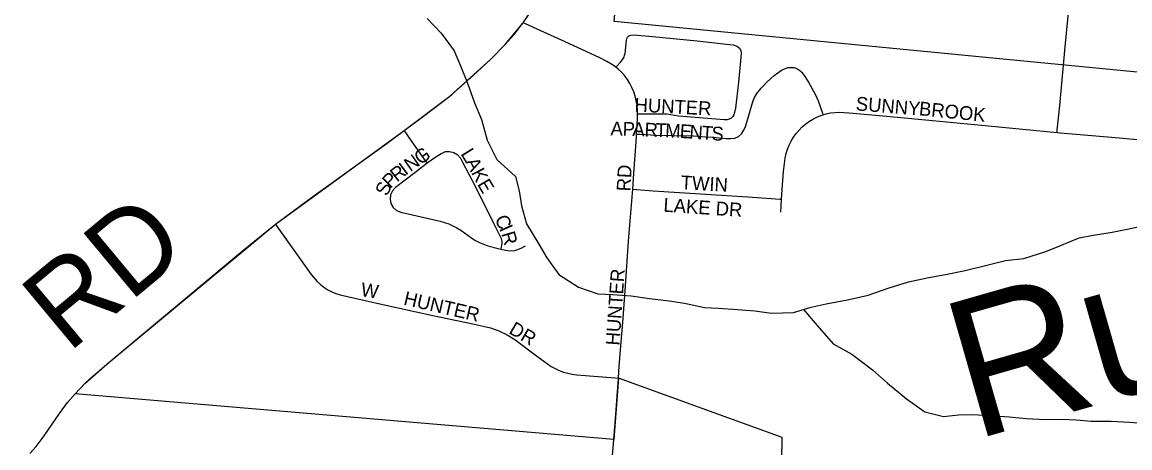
# Model space of a CAD drawing. Extents: x 1410790 to 1770854, y 566777 to 831614.
# Drawn here: x 1562528 to 1566542, y 678665 to 680208 of the extents above; entities that cross this region are included whole.
import ezdxf

# ---------------------------------------------------------------- set-up
doc = ezdxf.new("R2010")
doc.units = 0
for name, color, linetype in [('GM_X_City_Street', 7, 'Continuous'), ('GM_X_City_Street_Text', 7, 'Continuous'), ('GM_X_Corporation', 7, 'Continuous'), ('GM_X_County_Road', 7, 'Continuous'), ('GM_X_County_Road_Text', 7, 'Continuous'), ('GM_X_Minor_River', 7, 'Continuous'), ('GM_X_Minor_River_Text', 7, 'Continuous'), ('GM_X_Section', 7, 'Continuous')]:
    doc.layers.add(name, color=color, linetype=linetype)

msp = doc.modelspace()

# ---------------------------------------------------------------- linework, layer by layer
at = {"layer": 'GM_X_City_Street'}
for points in [[(1566278.5, 679807.9), (1566279.3, 679816.5), (1566287.8, 679906), (1566308, 680118.8), (1566322.3, 680267.4)], [(1564679.3, 680044.6), (1564670.4, 680051.4), (1564660.6, 680057.5), (1564646.1, 680065.8), (1564621.3, 680078.7), (1564493.8, 680137.6), (1564408.1, 680176.7), (1564352.3, 680201.4), (1564343.1, 680205.5)], [(1564679.3, 680044.6), (1564683.2, 680048.7), (1564696.7, 680063.1), (1564704.7, 680073.4), (1564709, 680081.2), (1564711.3, 680087.8), (1564712.8, 680094), (1564717.4, 680141.1), (1564718.7, 680148.2), (1564721.9, 680154), (1564727, 680158.3), (1564734.1, 680161.3), (1564744.2, 680161.7), (1564812.3, 680156.4), (1564973.8, 680140.1), (1565080.6, 680128.8), (1565104.7, 680125.6), (1565119.5, 680120.5), (1565127.8, 680113.5), (1565132.7, 680105.5), (1565133.7, 680096), (1565132.7, 680081), (1565123.8, 679990.2), (1565112.7, 679896.8), (1565109.5, 679880.6), (1565107.1, 679872.3), (1565103.1, 679865.6), (1565097.8, 679860), (1565090.5, 679855.8), (1565083, 679854.3), (1565071.4, 679853.5), (1564907.3, 679867.5), (1564892.3, 679870.2), (1564878.3, 679872.3), (1564862.7, 679874.2), (1564843.7, 679875), (1564770.9, 679874.2), (1564758, 679874)], [(1564758, 679874), (1564757.8, 679890), (1564756.2, 679906.6), (1564753.5, 679923.2), (1564749.4, 679939.5), (1564744.2, 679955.5), (1564737.8, 679971), (1564730.2, 679986), (1564721.4, 680000.3), (1564711.5, 680014), (1564700.2, 680026.5), (1564687.9, 680038), (1564679.3, 680044.6)], [(1564754.8, 679802.6), (1564766.7, 679801.8), (1564825.7, 679798), (1564881, 679797.3), (1564960.7, 679795.5), (1565003.8, 679792.9), (1565029.6, 679790.7), (1565078.6, 679785.9), (1565094.6, 679785.8), (1565110.1, 679787.6), (1565123.8, 679793.2), (1565134.9, 679803), (1565143.5, 679816), (1565149.4, 679830.4), (1565159.1, 679861.5), (1565173.1, 679911.8), (1565178, 679926.8), (1565181.7, 679935.3), (1565190.7, 679949.4), (1565206.4, 679968.2), (1565228, 679991.4), (1565252.6, 680014.2), (1565265.9, 680024.6), (1565280.3, 680034), (1565288.1, 680038), (1565296.5, 680041.4), (1565303.4, 680043.3), (1565310, 680044.2), (1565317, 680044.2), (1565323.9, 680043.4), (1565331.7, 680041.1), (1565338.8, 680038), (1565345.6, 680033.2), (1565352.4, 680026.4), (1565359, 680018.5), (1565377.1, 679990.4), (1565402, 679947.3), (1565408.2, 679933.5), (1565412.5, 679922.8), (1565427.7, 679877.9), (1565429.6, 679872.4)], [(1564754.8, 679802.6), (1564758.2, 679856.7), (1564758, 679874)], [(1565280.3, 679566), (1565282.6, 679601.1), (1565287.3, 679666.7), (1565293.5, 679715.5), (1565296.8, 679731.5), (1565301.4, 679747.3), (1565307.4, 679762.5), (1565314.7, 679777.2), (1565323.2, 679791.3), (1565332.9, 679804.5), (1565343.4, 679817.1), (1565354.9, 679828.9), (1565367.4, 679839.7), (1565381, 679849.3), (1565395.3, 679857.8), (1565410.3, 679865.2), (1565425.7, 679871.2), (1565429.6, 679872.4)], [(1565429.6, 679872.4), (1565441.6, 679876), (1565457.8, 679879.2), (1565474.2, 679881), (1565490.5, 679881.3), (1565539.7, 679878.1), (1565686.7, 679864.3), (1565801.1, 679853.5), (1566029.8, 679832.1), (1566278.5, 679807.9)], [(1563995.7, 679696.5), (1563978.1, 679721.5), (1563932.5, 679786), (1563917.8, 679807.5), (1563912.8, 679814.8)], [(1564740.4, 679602.9), (1564744.9, 679660), (1564754, 679791), (1564754.8, 679802.6)], [(1566278.5, 679807.9), (1566291.2, 679806.6), (1566503.7, 679788.8), (1566633.7, 679776.3)], [(1564264, 679385.2), (1564264.9, 679391.9), (1564267, 679406.3), (1564267, 679412.8), (1564266.3, 679418.2), (1564265.1, 679422.1), (1564236.5, 679480.8), (1564170.2, 679612), (1564125.4, 679699.2), (1564117.3, 679713.5), (1564106.6, 679725.6), (1564092.8, 679734.1), (1564077.1, 679738.4), (1564060.9, 679737.5), (1564046, 679731.2), (1564027.4, 679718.5), (1563995.7, 679696.5)], [(1563995.7, 679696.5), (1563950.4, 679662.2), (1563881.1, 679608.7), (1563869.7, 679597), (1563862.6, 679582.5), (1563861, 679566.3), (1563864.3, 679550.3), (1563872.3, 679536.1), (1563884.5, 679525.5), (1563899.7, 679519.7), (1564043, 679486.5), (1564058.7, 679482.1), (1564074.1, 679476.8), (1564089, 679470.2), (1564103.4, 679462.6), (1564117.3, 679454.1), (1564157, 679425.2), (1564170.9, 679416.8), (1564185.4, 679409.3), (1564215.8, 679397.6), (1564253.4, 679387.7), (1564264, 679385.2)], [(1564688.7, 678917.5), (1564691.6, 678962.3), (1564692.5, 678972.6), (1564695.4, 679005.3), (1564704.4, 679119.8), (1564713.2, 679234.3), (1564725.8, 679414.6), (1564740.4, 679602.9)], [(1564740.4, 679602.9), (1564756, 679601.7), (1564814.8, 679597.2), (1565157.4, 679574.3), (1565241.8, 679568.5), (1565273.7, 679566.4), (1565280.3, 679566)], [(1565277.2, 679519.2), (1565280.3, 679566)], [(1563445.5, 679475.2), (1563455.8, 679460.8), (1563575.6, 679293.5), (1563596.7, 679268.5), (1563608.5, 679257.1), (1563621.4, 679246.9), (1563635.2, 679238.1), (1563649.7, 679230.5), (1563664.8, 679224.2), (1563680.4, 679219.3), (1563824.3, 679187), (1564016.7, 679145.3), (1564161.1, 679114.5), (1564225, 679100), (1564255.9, 679089), (1564285.4, 679074.8), (1564313.2, 679057.4), (1564392.4, 678999), (1564431.4, 678969), (1564445.1, 678959.9), (1564459.4, 678952), (1564474.4, 678945.3), (1564489.8, 678939.7), (1564505.6, 678935.2), (1564521.6, 678931.6), (1564537.8, 678929.1), (1564676.5, 678918.5), (1564688.7, 678917.5)], [(1564264, 679385.2), (1564279.3, 679381.5), (1564295.4, 679379.5), (1564311.6, 679380), (1564324.5, 679383.4), (1564338.7, 679390.2), (1564351.7, 679397.6)], [(1564685.6, 678870.1), (1564686.4, 678882.2), (1564688.7, 678917.5)]]:
    msp.add_lwpolyline(points, dxfattribs=at)
at = {"layer": 'GM_X_Corporation'}
msp.add_lwpolyline([(1565279.2, 678536.4), (1565282.3, 678702.9), (1564688.7, 678917.5), (1564671.8, 678694.9), (1562719.4, 678861.1), (1562754.5, 678898), (1562834.8, 678968.3), (1563445.5, 679475.2), (1563912.8, 679814.8), (1564077.3, 679940), (1564226.4, 680074.3), (1564278.6, 680126.8), (1564343.1, 680205.5), (1564519.8, 680474.3)], dxfattribs=at)
at = {"layer": 'GM_X_County_Road'}
for points in [[(1564343.1, 680205.5), (1564387.9, 680270.9), (1564469.4, 680393.9), (1564519.8, 680474.3)], [(1563912.8, 679814.8), (1563982.8, 679866.9), (1564077.3, 679940), (1564086.6, 679947.2), (1564162.6, 680014.1), (1564226.4, 680074.3), (1564278.6, 680126.8), (1564311.4, 680163.9), (1564341.4, 680203.1), (1564343.1, 680205.5)], [(1563445.5, 679475.2), (1563571.2, 679568.6), (1563851.1, 679769), (1563912.8, 679814.8)], [(1562556, 678644.5), (1562578.1, 678669.3), (1562607.8, 678708.9), (1562663.5, 678790), (1562692.4, 678829.4), (1562719.4, 678861.1), (1562754.6, 678898.1), (1562772.8, 678914.9), (1562834.8, 678968.3), (1562960.5, 679073.5), (1563325.3, 679378.1), (1563439.8, 679470.9), (1563445.5, 679475.2)], [(1564314.6, 674908.5), (1564323.9, 675001), (1564340.4, 675164.4), (1564372.1, 675458.4), (1564397.7, 675703.6), (1564422.2, 675948.9), (1564463.2, 676407.2), (1564478.3, 676570.8), (1564499.5, 676799.7), (1564521.5, 677045.1), (1564554.4, 677388.5), (1564571.6, 677584.9), (1564602.8, 677928.6), (1564615.2, 678059.4), (1564633, 678239.1), (1564657.8, 678517), (1564671.8, 678694.9), (1564680.9, 678801.2), (1564685.6, 678870.1)]]:
    msp.add_lwpolyline(points, dxfattribs=at)
at = {"layer": 'GM_X_Minor_River'}
for points in [[(1563995.1, 680221.3), (1564046.4, 680168.6), (1564093.5, 680104), (1564116.7, 680049.7), (1564141.9, 679987.3), (1564167, 679915), (1564192.2, 679854.6), (1564213.2, 679780.3), (1564248.3, 679709.8), (1564315.4, 679649), (1564328.7, 679596.8)], [(1564328.7, 679596.8), (1564338, 679542.6), (1564355.1, 679476.4), (1564400.1, 679403.8), (1564429.5, 679353.4), (1564472.6, 679292.8), (1564543.9, 679247.9), (1564613.5, 679223), (1564667.3, 679220.3), (1564735.1, 679215.4), (1564800.9, 679206.6), (1564872.6, 679197.7), (1564928.4, 679188.9), (1565000.1, 679174), (1565051.9, 679171.3), (1565119.7, 679166.5), (1565183.5, 679161.7), (1565243.3, 679152.9), (1565323.2, 679155.9), (1565387.3, 679175.1), (1565441.3, 679186.4), (1565519.3, 679201.4), (1565593.4, 679218.4), (1565669.6, 679245.5), (1565739.7, 679266.6), (1565807.7, 679281.7), (1565879.7, 679294.8), (1565945.8, 679308), (1566023.8, 679327), (1566091.9, 679344.1), (1566157.9, 679351.3), (1566238, 679376.3), (1566288.2, 679397.7), (1566358.4, 679426.8), (1566410.4, 679436.1), (1566478.4, 679447.3), (1566538.4, 679458.5), (1566616.4, 679475.5)], [(1565359.1, 679166.6), (1565408.4, 679108.8), (1565467.5, 679042), (1565534.9, 679005.1), (1565610, 678948.1), (1565663.3, 678899.4), (1565732.4, 678842.5), (1565799.7, 678795.7), (1565867.4, 678778.8), (1565921.3, 678784.1), (1565973.2, 678785.4), (1566031.1, 678782.7), (1566104.9, 678777.8), (1566166.6, 678771), (1566236.5, 678768.1), (1566294.4, 678769.4), (1566348.2, 678766.7), (1566402, 678762), (1566473.9, 678761.1), (1566541.7, 678758.2), (1566599.5, 678753.5), (1566669.4, 678754.6), (1566733.1, 678741.8), (1566798.9, 678738.9)]]:
    msp.add_lwpolyline(points, dxfattribs=at)
at = {"layer": 'GM_X_Section'}
msp.add_lwpolyline([(1570366.9, 684817.2), (1570438.7, 684810.1), (1569973.9, 679696.7), (1564673.5, 680210.6), (1565148.5, 685333.7)], close=True, dxfattribs=at)

# ---------------------------------------------------------------- texts
at = {"layer": 'GM_X_City_Street_Text'}
for s, rotation, p in [('HUNTER', 357.0389, (1564746.3, 679884.2)), ('SUNNY', 355.2345, (1565547.6, 679888.6)), ('BROOK', 354.1724, (1565776.4, 679871)), ('A', 357.9562, (1564659.5, 679798.2)), ('P', 357.9507, (1564703.4, 679796.7)), ('A', 357.9605, (1564738.6, 679795.4)), ('R', 357.9477, (1564782.6, 679793.8)), ('T', 357.7596, (1564822.1, 679792.4)), ('M', 357.1212, (1564857.2, 679791.1)), ('E', 356.6095, (1564909.8, 679788.4)), ('N', 355.8552, (1564944.7, 679786.3)), ('T', 355.8171, (1564988.6, 679783.2)), ('S', 356.4871, (1565024.4, 679780.5)), ('G', 34.4083, (1563970.2, 679689.2)), ('L', 302.1516, (1564115.4, 679730.7)), ('N', 35.2087, (1563934.4, 679663.9)), ('R', 37.9335, (1563885.9, 679626.8)), ('I', 36.5464, (1563916.9, 679651)), ('A', 297.4644, (1564133.6, 679701.8)), ('K', 297.0734, (1564153.9, 679662.9)), ('RD', 86.9775, (1564732, 679593.7)), ('P', 45.5795, (1563862.6, 679602.9)), ('E', 300.5432, (1564175.5, 679620.8)), ('TWIN', 356.8219, (1564913.5, 679602.6)), ('S', 65.8489, (1563850.8, 679574.6)), ('LAKE DR', 356.1845, (1564850.7, 679521.2)), ('C', 293.6913, (1564239.4, 679496.3)), ('I', 293.7025, (1564255.3, 679460)), ('R', 286.1189, (1564263.5, 679441.5)), ('HUNTER', 85.9821, (1564692.4, 679034.7)), ('W', 351.2507, (1563752.8, 679215.3)), ('HUNTER', 347.0056, (1563907.5, 679184.4)), ('DR', 329.5437, (1564288.3, 679082.2))]:
    msp.add_text(s, height=50, rotation=rotation, dxfattribs=at).set_placement(p)
at = {"layer": 'GM_X_County_Road_Text'}
msp.add_text('RD', height=300, rotation=39.7412, dxfattribs=at).set_placement((1562694.3, 679005.9))
at = {"layer": 'GM_X_Minor_River_Text'}
msp.add_text('Run', height=499.95, rotation=15.9744, dxfattribs=at).set_placement((1565975.2, 678692))

doc.saveas('drawing.dxf')
